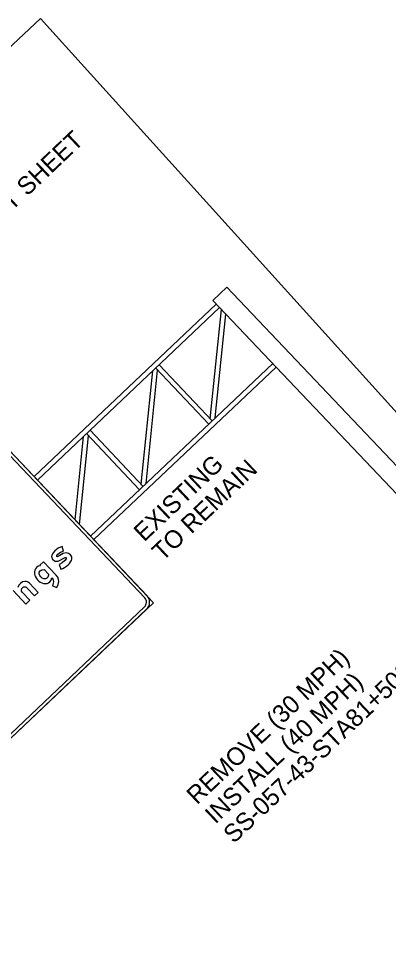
# Model space of a CAD drawing. Extents: x 1289840 to 1295361, y 220865 to 226414.
# Drawn here: x 1294014 to 1294138.5, y 225212.8 to 225526.9 of the extents above; entities that cross this region are included whole.
import ezdxf

# ---------------------------------------------------------------- set-up
doc = ezdxf.new("R2010")
doc.units = 0
for name, color, linetype in [('R_Annotation', 7, 'Continuous'), ('R_Border', 7, 'Continuous'), ('R_No Plot', 7, 'Continuous'), ('R_OVHD_Sign', 7, 'Continuous'), ('S_MISC_STRUCTURES', 7, 'Continuous')]:
    doc.layers.add(name, color=color, linetype=linetype)

msp = doc.modelspace()

# ---------------------------------------------------------------- linework, layer by layer
at = {"layer": 'R_No Plot'}
msp.add_lwpolyline([(1293463.51, 223873.73), (1293451.02, 223927.27), (1293084.88, 224313.59), (1293049.18, 224285.32), (1292886.4, 224457.07), (1293263.31, 224814.29), (1294021.34, 225526.85), (1294425.84, 225079.29), (1294588.32, 224942.91), (1294719.88, 224769.04), (1294177.05, 224254.57), (1293865.38, 223959.18), (1293708.84, 223976.93), (1293583.27, 224083.83), (1293485.04, 224003.92), (1293450.74, 223971.87), (1293580.16, 223892.04), (1293536.69, 223828.17)], close=True, dxfattribs=at)
at = {"layer": 'R_OVHD_Sign'}
for p, q in [((1294059.49, 225330.17), (1293999.12, 225393.86)), ((1294056.47, 225331.79), (1294000.57, 225390.76)), ((1294001.36, 225391.51), (1294057.25, 225332.53)), ((1294025.61, 225346.95), (1294025.24, 225346.23)), ((1294026.22, 225347.67), (1294025.61, 225346.95)), ((1294027.33, 225348.49), (1294026.22, 225347.67)), ((1294027.2, 225346.52), (1294028.08, 225347.15)), ((1294028.64, 225349.07), (1294027.33, 225348.49)), ((1294029.04, 225346.69), (1294027.94, 225346.12)), ((1294028.08, 225347.15), (1294029.17, 225347.55)), ((1294029.17, 225347.55), (1294028.64, 225349.07)), ((1294030, 225346.92), (1294029.04, 225346.69)), ((1294030.81, 225346.79), (1294030, 225346.92)), ((1294031.5, 225346.32), (1294030.81, 225346.79)), ((1294025.24, 225346.23), (1294025.15, 225345.78)), ((1294025.15, 225345.78), (1294025.18, 225345.37)), ((1294025.18, 225345.37), (1294025.32, 225345)), ((1294025.32, 225345), (1294025.57, 225344.66)), ((1294025.57, 225344.66), (1294025.94, 225344.35)), ((1294025.94, 225344.35), (1294026.35, 225344.18)), ((1294026.35, 225344.18), (1294026.81, 225344.13)), ((1294026.81, 225344.13), (1294027.32, 225344.21)), ((1294026.85, 225346.06), (1294027.2, 225346.52)), ((1294026.9, 225345.73), (1294026.85, 225346.06)), ((1294027.12, 225345.67), (1294026.9, 225345.73)), ((1294027.48, 225345.82), (1294027.12, 225345.67)), ((1294027.32, 225344.21), (1294028.04, 225344.49)), ((1294027.94, 225346.12), (1294027.48, 225345.82)), ((1294028.64, 225343.64), (1294027.71, 225343.07)), ((1294028.04, 225344.49), (1294029.03, 225345.02)), ((1294029.54, 225344.38), (1294028.64, 225343.64)), ((1294029.03, 225345.02), (1294029.71, 225345.36)), ((1294030.04, 225344.98), (1294029.54, 225344.38)), ((1294029.71, 225345.36), (1294030.04, 225345.35)), ((1294030.04, 225345.35), (1294030.04, 225344.98)), ((1294031.15, 225343.42), (1294031.52, 225343.89)), ((1294031.77, 225345.97), (1294031.5, 225346.32)), ((1294031.52, 225343.89), (1294031.78, 225344.35)), ((1294031.94, 225345.59), (1294031.77, 225345.97)), ((1294031.78, 225344.35), (1294031.94, 225344.78)), ((1294031.99, 225345.2), (1294031.94, 225345.59)), ((1294031.94, 225344.78), (1294031.99, 225345.2)), ((1294027.71, 225343.07), (1294028.27, 225341.51)), ((1294028.27, 225341.51), (1294028.89, 225341.72)), ((1294028.89, 225341.72), (1294029.5, 225342.03)), ((1294029.5, 225342.03), (1294030.09, 225342.43)), ((1294030.09, 225342.43), (1294030.67, 225342.92)), ((1294030.67, 225342.92), (1294031.15, 225343.42)), ((1294015.34, 225337.16), (1294014.64, 225336.69)), ((1294016.15, 225337.34), (1294015.34, 225337.16)), ((1294016.57, 225337.32), (1294016.15, 225337.34)), ((1294016.97, 225337.22), (1294016.57, 225337.32)), ((1294017.32, 225337.02), (1294016.97, 225337.22)), ((1294012.2, 225334.27), (1294016.5, 225329.73)), ((1294014.1, 225336.03), (1294013.76, 225335.29)), ((1294014.64, 225336.69), (1294014.1, 225336.03)), ((1294015.01, 225334.5), (1294015.12, 225334.9)), ((1294015.04, 225334.07), (1294015.01, 225334.5)), ((1294015.23, 225333.74), (1294015.04, 225334.07)), ((1294015.12, 225334.9), (1294015.34, 225335.22)), ((1294015.34, 225335.22), (1294015.7, 225335.46)), ((1294015.7, 225335.46), (1294016.09, 225335.55)), ((1294016.09, 225335.55), (1294016.48, 225335.46)), ((1294016.48, 225335.46), (1294016.82, 225335.21)), ((1294016.82, 225335.21), (1294019.41, 225332.48)), ((1294017.65, 225336.75), (1294017.32, 225337.02)), ((1294020.61, 225333.62), (1294017.65, 225336.75)), ((1294017.83, 225330.99), (1294015.23, 225333.74)), ((1294016.5, 225329.73), (1294017.83, 225330.99)), ((1294019.41, 225332.48), (1294020.61, 225333.62)), ((1294056.47, 225331.79), (1294056.47, 225331.79)), ((1294056.47, 225331.79), (1294056.47, 225331.79)), ((1293974.57, 225249.69), (1294059.49, 225330.17)), ((1293976.18, 225252.71), (1294056.38, 225328.73)), ((1294057.13, 225327.94), (1293976.93, 225251.93))]:
    msp.add_line(p, q, dxfattribs=at)
for points in [[(1294025.43, 225335.85), (1294026.94, 225335.26), (1294027.34, 225336.35), (1294027.51, 225337.28), (1294027.49, 225338), (1294027.22, 225338.72), (1294026.68, 225339.44), (1294022.41, 225343.95), (1294021.2, 225342.81), (1294021.39, 225342.61), (1294020.66, 225342.44), (1294020.09, 225342.08), (1294019.71, 225341.63), (1294019.47, 225341.13), (1294019.35, 225340.57), (1294019.37, 225339.95), (1294019.49, 225339.37), (1294019.7, 225338.83), (1294020.01, 225338.31), (1294020.41, 225337.83), (1294020.85, 225337.42), (1294021.33, 225337.1), (1294021.85, 225336.85), (1294022.41, 225336.68), (1294023.04, 225336.59), (1294023.6, 225336.65), (1294024.1, 225336.83), (1294024.54, 225337.16), (1294025.02, 225337.79), (1294025.24, 225338.53), (1294025.37, 225338.41), (1294025.71, 225337.85), (1294025.77, 225337.16), (1294025.43, 225335.85)], [(1294024.05, 225339.8), (1294024.06, 225339.44), (1294023.98, 225339.09), (1294023.81, 225338.77), (1294023.54, 225338.47), (1294023.05, 225338.2), (1294022.46, 225338.25), (1294021.96, 225338.48), (1294021.5, 225338.86), (1294021.13, 225339.35), (1294020.94, 225339.86), (1294020.97, 225340.43), (1294021.28, 225340.91), (1294021.87, 225341.27), (1294022.61, 225341.33), (1294024.05, 225339.8)]]:
    msp.add_lwpolyline(points, dxfattribs=at)
for radius in [2.17, 3.25]:
    msp.add_arc((1294054.89, 225330.3), radius, 313.4637, 43.4639, dxfattribs=at)
at = {"layer": 'S_MISC_STRUCTURES'}
for p, q in [((1294079.46, 225431.94), (1294084.18, 225436.41)), ((1294157.72, 225358.81), (1294084.18, 225436.41)), ((1294153.01, 225354.34), (1294079.46, 225431.94)), ((1294019.25, 225372.63), (1294080.58, 225430.76)), ((1294020.36, 225371.46), (1294081.69, 225429.58)), ((1294078.57, 225392.12), (1294082.32, 225428.92)), ((1294080.23, 225392.38), (1294083.8, 225427.36)), ((1294038.25, 225352.58), (1294099.58, 225410.71)), ((1294039.37, 225351.4), (1294100.7, 225409.53)), ((1294061.35, 225410.3), (1294079.23, 225391.43)), ((1294055.28, 225370.05), (1294059.17, 225408.23)), ((1294056.94, 225370.3), (1294060.83, 225408.49)), ((1294060.17, 225409.18), (1294078.05, 225390.31)), ((1294038.06, 225388.22), (1294055.94, 225369.35)), ((1294033.02, 225358.1), (1294035.88, 225386.16)), ((1294034.49, 225356.55), (1294037.54, 225386.41)), ((1294036.88, 225387.1), (1294054.76, 225368.23))]:
    msp.add_line(p, q, dxfattribs=at)

# ---------------------------------------------------------------- texts
at = {"layer": 'R_Annotation'}
for s, p in [('EXISTING', (1294056.28, 225350.45)), ('TO REMAIN', (1294062.47, 225343.91)), ('REMOVE (30 MPH)', (1294074.08, 225261.91)), ('SS-057-43-STA81+50SB', (1294086.46, 225248.84)), ('INSTALL (40 MPH)', (1294080.27, 225255.38))]:
    msp.add_text(s, height=6, rotation=43.4387, dxfattribs=at).set_placement(p)
at = {"layer": 'R_Border'}
msp.add_text('SIGN PLACEMENT SHEET', height=6, rotation=43.4654, dxfattribs=at).set_placement((1293963.82, 225416.55))

doc.saveas('drawing.dxf')
